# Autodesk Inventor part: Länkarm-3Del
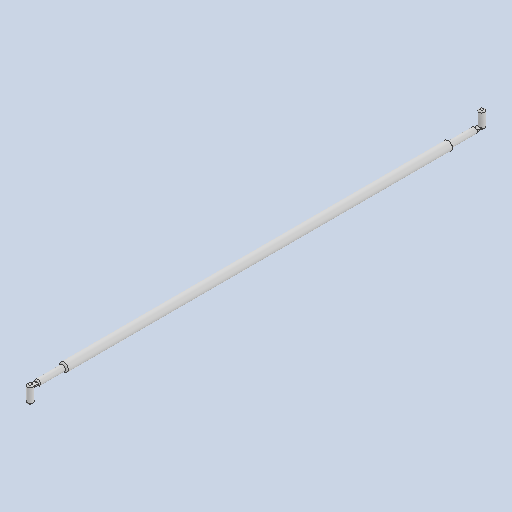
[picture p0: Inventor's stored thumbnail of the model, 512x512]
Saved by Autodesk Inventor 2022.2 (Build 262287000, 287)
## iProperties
Created: 2022-03
Part Number: Länkarm-3Del
Material: Generic
Document SubType Name: Modeling
Designer: cl
Density: 1 g/cm^3
Appearance: Default
Author: cl
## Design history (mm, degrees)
sketch "Sketch1"
  geometry: L1 (0, 0)-(0, -1497.36); L2 (0, 0)-(-10, 0); L3 (-10, 0)-(-10, -90); L4 (-10, -90)-(-15, -90); L5 (-15, -90)-(-15, -1407.36); L6 (0, -1497.36)-(-10, -1497.36); L7 (-10, -1497.36)-(-10, -1407.36); L8 (-10, -1407.36)-(-15, -1407.36); 1 further point
  constraints: 16 end point, 5 perpendicular, 2 horizontal, 1 midpoint, 1 vertical
  dimensions: "d0" = 1497.36 distance of L1.start L1.end (computed from BladBredd); "d1" = 20 diameter of L3 L1; "d2" = 5 distance between parallel lines of L3 L5; "d3" = 90 distance of L2.end L3.end; "d4" = 20 diameter of L7 L1; "d5" = 90 vertical distance of point (-5, -1497.36) L5.end
revolve "Revolution1" sketch "Sketch1" stored, may be unused: angle "d6" = 90 deg
fillet "Fillet1" dims "d7" = 5
workplane "Work Plane1"
sketch "Sketch2"
  geometry: L1 (10, 0)-(-10, 0) reference; L2 (7.5, 0)-(-7.5, 0); L3 (-7.5, 0)-(-7.5, 20); L4 (-7.5, 20)-(7.5, 20); L5 (7.5, 20)-(7.5, 0); L6 (10, -90)-(10, 0) reference; L7 (10, -1497.36)-(-10, -1497.36) reference; L8 (7.5, -1497.36)-(-7.5, -1497.36); L9 (-7.5, -1497.36)-(-7.5, -1517.36); L10 (-7.5, -1517.36)-(7.5, -1517.36); L11 (7.5, -1517.36)-(7.5, -1497.36); 3 further points
  constraints: 16 end point, 4 parallel, 2 horizontal, 2 perpendicular, 2 point on line, 1 collinear
  dimensions: "d9" = 2.5 distance between parallel lines of L5 L6; "d10" = 15 distance of L3.end L4.end; "d11" = 20 distance of L2.end L3.end; "d12" = 20 distance of L8.end L9.end; "d13" = 15 distance of L9.end L10.end
extrude "Extrusion1" join sketch "Sketch2" distance "d14" = 4; taper "d15" = 0 deg
sketch "Sketch3"
  geometry: L1 (7.5, 20)-(-7.5, 20) reference; L2 (-7.5, -1517.36)-(7.5, -1517.36) reference; C1 r 10 at (0, 20); C2 r 10 at (0, -1517.36); 1 further point
  constraints: 2 centre point, 2 midpoint
  dimensions: "d16" = 20 diameter of C1; "d17" = 20 diameter of C2
extrude "Extrusion2" join sketch "Sketch3" distance "d18" = 8; taper "d20" = 0 deg; dims "d19" = 48, "d21" = 0
extrude "Extrusion3" join sketch "Sketch3" distance "d22" = 50; taper "d24" = 0 deg; dims "d23" = 6, "d25" = 0
fillet "Fillet2" dims "d26" = 5
body "Solid1"
other parameters: "BladBredd" = 987.5, "Fönsterhöjd" = 862, "Blad2" = 1012.5, "Blad3" = 0, "Blad4" = 0, "Blad5" = 1012.5, "Blad6" = 2025, "MGJ12Djup" = 0, "MGJ12Bredd" = 0, "MGJ2Djup" = 0, "MGJ2Bredd" = 5012.5, "MGJ56Djup" = 0, "MGJ56Bredd" = 0, "MGJ23Djup" = 48, "MGJ45Djup" = 48, "GarageRegel5" = 0, "GarageRegel6" = 0, "Styrrulle2Djup" = 0, "FönsterhöjdStyrning" = 862, "FönsterKarm" = 54, "AndraGlasraden" = 0, "BrösthöjdStyrning2" = 0.0001, "InfälldGångDörr" = 0, "Infälldstyr" = 1030.33333, "EnDelGångDörr" = 0, "VinkelJärnStyrSkena" = 1456.25, "d8" = -2
